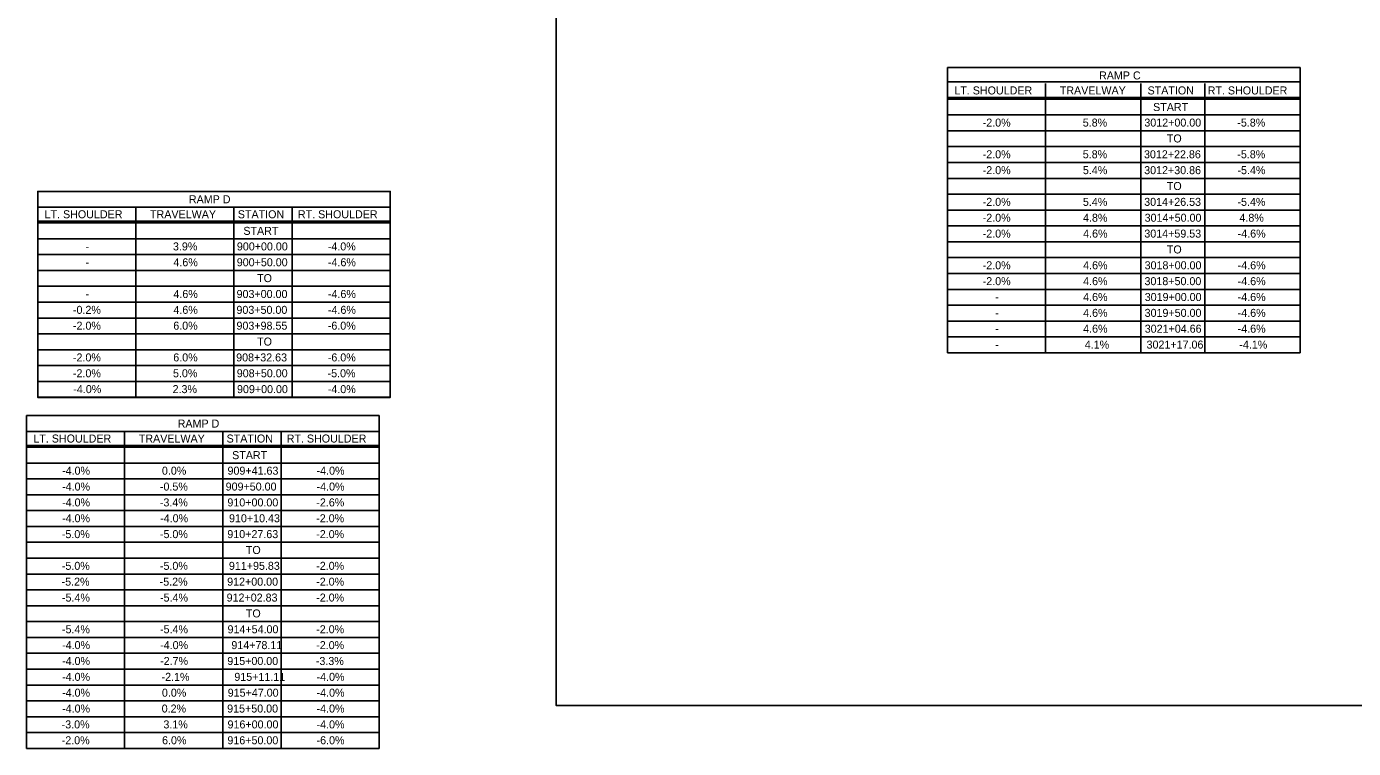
# Model space of a CAD drawing. Extents: x -15319374 to 1762012, y 465773 to 3693661.
# Drawn here: x -15314663 to -15314165.5, y 3691311.9 to 3691582.5 of the extents above; entities that cross this region are included whole.
import ezdxf

# ---------------------------------------------------------------- set-up
doc = ezdxf.new("R2010")
doc.units = 0
doc.layers.add('BORDER', color=7, linetype='Continuous')
doc.layers.add('DIMENSIONS', color=7, linetype='Continuous')

msp = doc.modelspace()

# ---------------------------------------------------------------- linework, layer by layer
at = {"layer": 'BORDER'}
for p, q in [((-15314317.7, 3691561.17), (-15314317.7, 3691483.98)), ((-15314280.93, 3691561.17), (-15314280.93, 3691460.21)), ((-15314245.16, 3691561.17), (-15314245.16, 3691460.21)), ((-15314221.29, 3691561.17), (-15314221.29, 3691460.21)), ((-15314185.52, 3691561.17), (-15314185.52, 3691483.98)), ((-15314317.7, 3691555.89), (-15314185.52, 3691555.89)), ((-15314317.7, 3691555.3), (-15314185.52, 3691555.3)), ((-15314317.7, 3691549.35), (-15314185.52, 3691549.35)), ((-15314317.7, 3691549.35), (-15314185.52, 3691549.35)), ((-15314317.7, 3691549.35), (-15314185.52, 3691549.35)), ((-15314317.7, 3691543.41), (-15314185.52, 3691543.41)), ((-15314317.7, 3691537.47), (-15314185.52, 3691537.47)), ((-15314317.7, 3691531.53), (-15314185.52, 3691531.53)), ((-15314317.7, 3691525.58), (-15314185.52, 3691525.58)), ((-15314317.7, 3691519.64), (-15314185.52, 3691519.64)), ((-15314658.77, 3691514.76), (-15314658.77, 3691443.45)), ((-15314622, 3691514.76), (-15314622, 3691443.45)), ((-15314585.23, 3691514.76), (-15314585.23, 3691443.45)), ((-15314563.36, 3691514.76), (-15314563.36, 3691443.45)), ((-15314317.7, 3691513.7), (-15314185.52, 3691513.7)), ((-15314658.77, 3691509.48), (-15314526.59, 3691509.48)), ((-15314658.77, 3691508.89), (-15314526.59, 3691508.89)), ((-15314317.7, 3691507.76), (-15314185.52, 3691507.76)), ((-15314658.77, 3691502.94), (-15314526.59, 3691502.94)), ((-15314658.77, 3691502.94), (-15314526.59, 3691502.94)), ((-15314658.77, 3691502.94), (-15314526.59, 3691502.94)), ((-15314317.7, 3691501.81), (-15314185.52, 3691501.81)), ((-15314658.77, 3691497), (-15314526.59, 3691497)), ((-15314317.7, 3691495.87), (-15314185.52, 3691495.87)), ((-15314658.77, 3691491.06), (-15314526.59, 3691491.06)), ((-15314317.7, 3691489.93), (-15314185.52, 3691489.93)), ((-15314658.77, 3691485.12), (-15314526.59, 3691485.12)), ((-15314317.7, 3691483.98), (-15314185.52, 3691483.98)), ((-15314658.77, 3691479.17), (-15314526.59, 3691479.17)), ((-15314317.7, 3691478.04), (-15314185.52, 3691478.04)), ((-15314658.77, 3691473.23), (-15314526.59, 3691473.23)), ((-15314317.7, 3691472.1), (-15314185.52, 3691472.1)), ((-15314658.77, 3691467.29), (-15314526.59, 3691467.29)), ((-15314317.7, 3691466.16), (-15314185.52, 3691466.16)), ((-15314658.77, 3691461.35), (-15314526.59, 3691461.35)), ((-15314317.7, 3691460.21), (-15314185.52, 3691460.21)), ((-15314658.77, 3691455.4), (-15314526.59, 3691455.4)), ((-15314658.77, 3691449.46), (-15314526.59, 3691449.46)), ((-15314658.77, 3691443.52), (-15314526.59, 3691443.52)), ((-15314662.98, 3691430.71), (-15314662.98, 3691312.51)), ((-15314626.21, 3691430.71), (-15314626.21, 3691311.92)), ((-15314589.44, 3691430.71), (-15314589.44, 3691311.92)), ((-15314567.57, 3691430.71), (-15314567.57, 3691311.92)), ((-15314662.98, 3691425.43), (-15314530.8, 3691425.43)), ((-15314662.98, 3691424.83), (-15314530.8, 3691424.83)), ((-15314662.98, 3691418.89), (-15314530.8, 3691418.89)), ((-15314662.98, 3691418.89), (-15314530.8, 3691418.89)), ((-15314662.98, 3691418.89), (-15314530.8, 3691418.89)), ((-15314662.98, 3691412.95), (-15314530.8, 3691412.95)), ((-15314662.98, 3691407), (-15314530.8, 3691407)), ((-15314662.98, 3691401.06), (-15314530.8, 3691401.06)), ((-15314662.98, 3691395.12), (-15314530.8, 3691395.12)), ((-15314662.98, 3691389.18), (-15314530.8, 3691389.18)), ((-15314662.98, 3691383.23), (-15314530.8, 3691383.23)), ((-15314662.98, 3691377.29), (-15314530.8, 3691377.29)), ((-15314662.98, 3691371.35), (-15314530.8, 3691371.35)), ((-15314662.98, 3691365.41), (-15314530.8, 3691365.41)), ((-15314662.98, 3691359.46), (-15314530.8, 3691359.46)), ((-15314662.98, 3691353.52), (-15314530.8, 3691353.52)), ((-15314662.98, 3691347.58), (-15314530.8, 3691347.58)), ((-15314662.98, 3691341.63), (-15314530.8, 3691341.63)), ((-15314662.98, 3691335.69), (-15314530.8, 3691335.69)), ((-15314662.98, 3691329.75), (-15314530.8, 3691329.75)), ((-15314662.98, 3691323.81), (-15314530.8, 3691323.81)), ((-15314662.98, 3691317.86), (-15314530.8, 3691317.86))]:
    msp.add_line(p, q, dxfattribs=at)
for points in [[(-15314464.43, 3691853.02), (-15313664.43, 3691853.02), (-15313664.43, 3691328.02), (-15314464.43, 3691328.02)], [(-15314317.7, 3691561.77), (-15314185.52, 3691561.77), (-15314185.52, 3691460.21), (-15314317.7, 3691460.21)], [(-15314658.77, 3691514.76), (-15314526.59, 3691514.76), (-15314526.59, 3691443.45), (-15314658.77, 3691443.45)], [(-15314662.98, 3691430.71), (-15314530.8, 3691430.71), (-15314530.8, 3691311.92), (-15314662.98, 3691311.92)]]:
    msp.add_lwpolyline(points, close=True, dxfattribs=at)
for points in [[(-15314317.7, 3691561.17), (-15314317.7, 3691567.12), (-15314185.52, 3691567.12), (-15314185.52, 3691561.17)], [(-15314658.77, 3691514.76), (-15314658.77, 3691520.71), (-15314526.59, 3691520.71), (-15314526.59, 3691514.76)], [(-15314662.98, 3691430.71), (-15314662.98, 3691436.65), (-15314530.8, 3691436.65), (-15314530.8, 3691430.71)]]:
    msp.add_lwpolyline(points, dxfattribs=at)

# ---------------------------------------------------------------- texts
at = {"layer": 'DIMENSIONS'}
for s, p in [('RAMP C', (-15314260.88, 3691562.65)), ('LT. SHOULDER', (-15314315.14, 3691557.03)), ('STATION', (-15314242.7, 3691557.03)), ('RT. SHOULDER', (-15314220.16, 3691557.03)), ('TRAVELWAY', (-15314275.61, 3691557.03)), ('START', (-15314240.62, 3691550.81)), ('-2.0%', (-15314304.51, 3691544.98)), ('5.8%', (-15314266.99, 3691544.98)), ('3012+00.00', (-15314243.9, 3691544.98)), ('-5.8%', (-15314209.05, 3691544.98)), ('TO', (-15314235.47, 3691539.04)), ('-2.0%', (-15314304.51, 3691533.1)), ('5.8%', (-15314266.99, 3691533.1)), ('3012+22.86', (-15314244.04, 3691533.1)), ('-5.8%', (-15314209.05, 3691533.1)), ('-2.0%', (-15314304.51, 3691527.15)), ('3012+30.86', (-15314243.97, 3691527.15)), ('5.4%', (-15314266.94, 3691527.15)), ('-5.4%', (-15314209, 3691527.15)), ('TO', (-15314235.47, 3691521.21)), ('RAMP D', (-15314602.11, 3691516.24)), ('-2.0%', (-15314304.51, 3691515.27)), ('5.4%', (-15314266.94, 3691515.27)), ('3014+26.53', (-15314243.96, 3691515.27)), ('-5.4%', (-15314209, 3691515.27)), ('LT. SHOULDER', (-15314656.21, 3691510.62)), ('TRAVELWAY', (-15314616.68, 3691510.62)), ('STATION', (-15314583.77, 3691510.62)), ('RT. SHOULDER', (-15314561.23, 3691510.62)), ('-2.0%', (-15314304.51, 3691509.32)), ('4.8%', (-15314266.89, 3691509.32)), ('3014+50.00', (-15314243.8, 3691509.32)), ('4.8%', (-15314208.25, 3691509.32)), ('START', (-15314581.69, 3691504.4)), ('-2.0%', (-15314304.51, 3691503.38)), ('4.6%', (-15314266.84, 3691503.38)), ('3014+59.53', (-15314243.91, 3691503.38)), ('-4.6%', (-15314208.91, 3691503.38)), ('3.9%', (-15314608.08, 3691498.57)), ('900+00.00', (-15314584.12, 3691498.57)), ('-4.0%', (-15314550.03, 3691498.57)), ('TO', (-15314235.47, 3691497.44)), ('-', (-15314640.89, 3691498.57)), ('4.6%', (-15314607.91, 3691492.63)), ('900+50.00', (-15314584.16, 3691492.63)), ('-4.6%', (-15314549.98, 3691492.63)), ('-', (-15314640.89, 3691492.63)), ('-2.0%', (-15314304.51, 3691491.5)), ('4.6%', (-15314266.84, 3691491.5)), ('3018+00.00', (-15314243.8, 3691491.5)), ('-4.6%', (-15314208.91, 3691491.5)), ('TO', (-15314576.54, 3691486.69)), ('-2.0%', (-15314304.51, 3691485.55)), ('4.6%', (-15314266.84, 3691485.55)), ('3018+50.00', (-15314243.85, 3691485.55)), ('-4.6%', (-15314208.91, 3691485.55)), ('-', (-15314640.89, 3691480.74)), ('4.6%', (-15314607.91, 3691480.74)), ('903+00.00', (-15314584.23, 3691480.74)), ('-4.6%', (-15314549.98, 3691480.74)), ('-', (-15314299.82, 3691479.61)), ('4.6%', (-15314266.84, 3691479.61)), ('3019+00.00', (-15314243.76, 3691479.61)), ('-4.6%', (-15314208.91, 3691479.61)), ('-0.2%', (-15314645.58, 3691474.8)), ('4.6%', (-15314607.91, 3691474.8)), ('903+50.00', (-15314584.28, 3691474.8)), ('-4.6%', (-15314549.98, 3691474.8)), ('4.6%', (-15314266.84, 3691473.67)), ('3019+50.00', (-15314243.8, 3691473.67)), ('-4.6%', (-15314208.91, 3691473.67)), ('-2.0%', (-15314645.58, 3691468.86)), ('6.0%', (-15314607.96, 3691468.86)), ('903+98.55', (-15314584.27, 3691468.86)), ('-6.0%', (-15314550.03, 3691468.86)), ('-', (-15314299.82, 3691473.67)), ('4.6%', (-15314266.84, 3691467.73)), ('3021+04.66', (-15314243.76, 3691467.73)), ('-4.6%', (-15314208.91, 3691467.73)), ('TO', (-15314576.54, 3691462.91)), ('-', (-15314299.82, 3691467.73)), ('-', (-15314299.82, 3691461.78)), ('4.1%', (-15314266.23, 3691461.78)), ('3021+17.06', (-15314243.07, 3691461.78)), ('-4.1%', (-15314208.29, 3691461.78)), ('-2.0%', (-15314645.58, 3691456.97)), ('6.0%', (-15314607.96, 3691456.97)), ('908+32.63', (-15314584.39, 3691456.97)), ('-6.0%', (-15314550.03, 3691456.97)), ('-2.0%', (-15314645.58, 3691451.03)), ('5.0%', (-15314608.06, 3691451.03)), ('908+50.00', (-15314584.16, 3691451.03)), ('-5.0%', (-15314550.12, 3691451.03)), ('-4.0%', (-15314645.44, 3691445.09)), ('2.3%', (-15314608.22, 3691445.09)), ('909+00.00', (-15314584.07, 3691445.09)), ('-4.0%', (-15314550.03, 3691445.09)), ('RAMP D', (-15314606.32, 3691432.18)), ('LT. SHOULDER', (-15314660.42, 3691426.57)), ('TRAVELWAY', (-15314620.89, 3691426.57)), ('STATION', (-15314587.98, 3691426.57)), ('RT. SHOULDER', (-15314565.44, 3691426.57)), ('START', (-15314585.9, 3691420.34)), ('-4.0%', (-15314649.65, 3691414.52)), ('0.0%', (-15314612.22, 3691414.52)), ('909+41.63', (-15314587.63, 3691414.52)), ('-4.0%', (-15314554.24, 3691414.52)), ('-4.0%', (-15314649.65, 3691408.57)), ('-0.5%', (-15314612.97, 3691408.57)), ('909+50.00', (-15314588.33, 3691408.57)), ('-4.0%', (-15314554.24, 3691408.57)), ('-4.0%', (-15314649.65, 3691402.63)), ('-3.4%', (-15314613, 3691402.63)), ('910+00.00', (-15314587.67, 3691402.63)), ('-2.6%', (-15314554.33, 3691402.63)), ('-4.0%', (-15314649.65, 3691396.69)), ('-4.0%', (-15314612.88, 3691396.69)), ('910+10.43', (-15314587.06, 3691396.69)), ('-2.0%', (-15314554.38, 3691396.69)), ('-5.0%', (-15314649.74, 3691390.75)), ('-5.0%', (-15314612.97, 3691390.75)), ('910+27.63', (-15314587.7, 3691390.75)), ('-2.0%', (-15314554.38, 3691390.75)), ('TO', (-15314580.75, 3691384.8)), ('-5.0%', (-15314649.74, 3691378.86)), ('-5.0%', (-15314612.97, 3691378.86)), ('911+95.83', (-15314587.11, 3691378.86)), ('-2.0%', (-15314554.38, 3691378.86)), ('-5.2%', (-15314649.84, 3691372.92)), ('-5.2%', (-15314613.07, 3691372.92)), ('912+00.00', (-15314587.76, 3691372.92)), ('-2.0%', (-15314554.38, 3691372.92)), ('-5.4%', (-15314649.69, 3691366.97)), ('-5.4%', (-15314612.93, 3691366.97)), ('912+02.83', (-15314587.96, 3691366.97)), ('-2.0%', (-15314554.38, 3691366.97)), ('TO', (-15314580.75, 3691361.03)), ('-5.4%', (-15314649.69, 3691355.09)), ('-5.4%', (-15314612.93, 3691355.09)), ('914+54.00', (-15314587.62, 3691355.09)), ('-2.0%', (-15314554.38, 3691355.09)), ('-4.0%', (-15314649.65, 3691349.15)), ('-4.0%', (-15314612.88, 3691349.15)), ('914+78.11', (-15314586.18, 3691349.15)), ('-2.0%', (-15314554.38, 3691349.15)), ('-4.0%', (-15314649.65, 3691343.2)), ('-2.7%', (-15314612.9, 3691343.2)), ('915+00.00', (-15314587.71, 3691343.2)), ('-3.3%', (-15314554.52, 3691343.2)), ('-4.0%', (-15314649.65, 3691337.26)), ('-2.1%', (-15314612.36, 3691337.26)), ('915+11.11', (-15314585.07, 3691337.26)), ('-4.0%', (-15314554.24, 3691337.26)), ('-4.0%', (-15314649.65, 3691331.32)), ('0.0%', (-15314612.22, 3691331.32)), ('915+47.00', (-15314587.55, 3691331.32)), ('-4.0%', (-15314554.24, 3691331.32)), ('-4.0%', (-15314649.65, 3691325.38)), ('0.2%', (-15314612.31, 3691325.38)), ('915+50.00', (-15314587.76, 3691325.38)), ('-4.0%', (-15314554.24, 3691325.38)), ('-3.0%', (-15314649.81, 3691319.43)), ('3.1%', (-15314611.67, 3691319.43)), ('916+00.00', (-15314587.62, 3691319.43)), ('-4.0%', (-15314554.24, 3691319.43)), ('-2.0%', (-15314649.79, 3691313.49)), ('6.0%', (-15314612.17, 3691313.49)), ('916+50.00', (-15314587.67, 3691313.49)), ('-6.0%', (-15314554.24, 3691313.49))]:
    msp.add_text(s, height=3, dxfattribs=at).set_placement(p)

doc.saveas('drawing.dxf')
